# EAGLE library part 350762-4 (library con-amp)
Universal MATE-N-LOK .250" Centerline, 600 V, 19 - 36 A max Source: http://catalog.tycoelectronics.com/ .. ENG_CD_350762_N.pdf
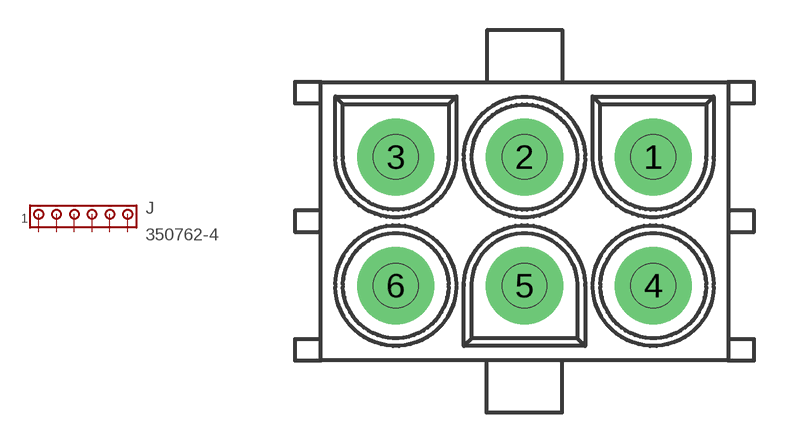
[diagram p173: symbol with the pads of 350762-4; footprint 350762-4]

Designator prefix J

## 350762-4 (MF: TYCO ELECTRONICS; MPN: 350762-4; OC_FARNELL: 1908157; OC_NEWARK: 92F8426)  [350762-4]
1  1  pas
2  2  pas
3  3  pas
4  4  pas
5  5  pas
6  6  pas

## Footprint 350762-4 (pad centres in mm)
Universal MATE-N-LOK .250" Centerline, 600 V, 19 - 36 A max Source: http://catalog.tycoelectronics.com/ .. ENG_CD_350762_N.pdf
drill 1.8 pad 3.81 round: 1 6.35,3.175; 2 0,3.175; 3 -6.35,3.175; 4 6.35,-3.175; 5 0,-3.175; 6 -6.35,-3.175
